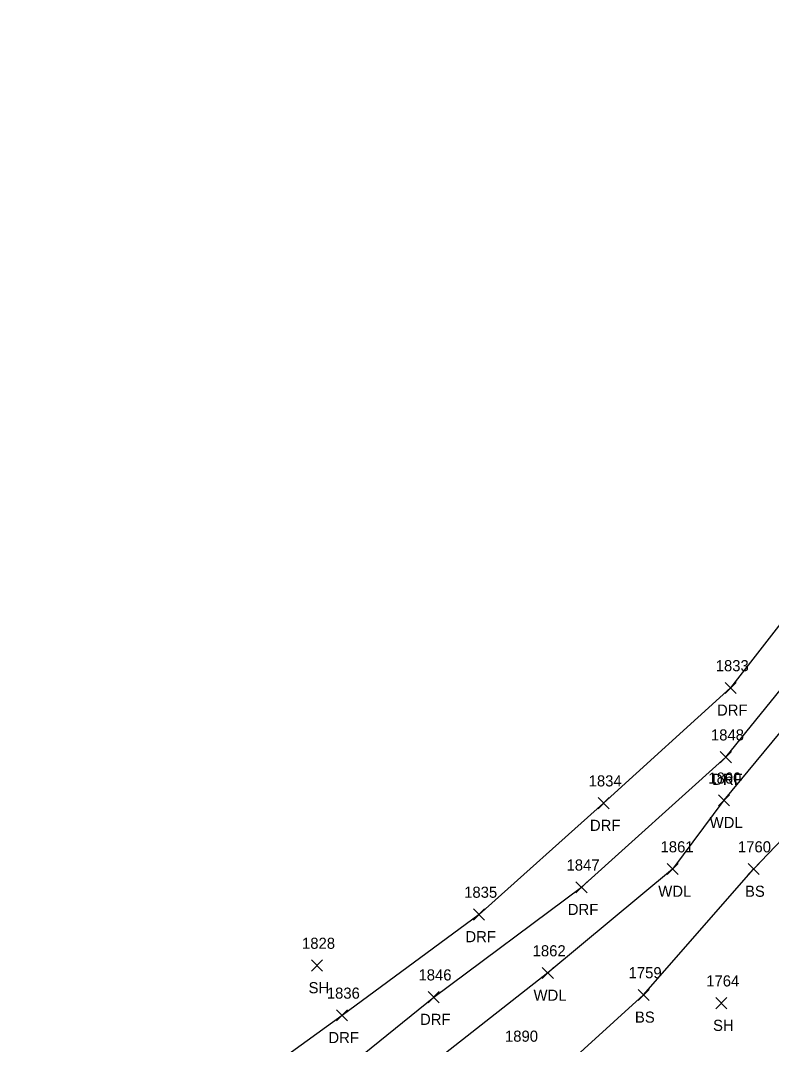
# Model space of a CAD drawing. Extents: x 1621633 to 1624015, y 417863 to 420979.
# Drawn here: x 1621756.1 to 1621891.2, y 418122.7 to 418307.1 of the extents above; entities that cross this region are included whole.
import ezdxf

# ---------------------------------------------------------------- set-up
doc = ezdxf.new("R2010")
doc.units = 0
for name, color, linetype in [('L_A', 7, 'Continuous'), ('L_I', 7, 'Continuous'), ('L_TIC', 7, 'Continuous'), ('LAWA', 7, 'Continuous'), ('LELB', 7, 'Continuous'), ('R_A', 7, 'Continuous'), ('R_I', 7, 'Continuous'), ('R_TIC', 7, 'Continuous'), ('RDF', 7, 'Continuous')]:
    doc.layers.add(name, color=color, linetype=linetype)

msp = doc.modelspace()

# ---------------------------------------------------------------- linework, layer by layer
at = {"layer": 'L_TIC'}
for points in [[(1621881.69, 418165.67), (1621883.69, 418167.67)], [(1621883.69, 418165.67), (1621881.69, 418167.67)], [(1621872.44, 418153.29), (1621874.44, 418155.29)], [(1621874.44, 418153.29), (1621872.44, 418155.29)], [(1621887.03, 418153.29), (1621889.03, 418155.29)], [(1621889.03, 418153.29), (1621887.03, 418155.29)], [(1621808.43, 418135.92), (1621810.43, 418137.92)], [(1621810.43, 418135.92), (1621808.43, 418137.92)], [(1621849.99, 418134.57), (1621851.99, 418136.57)], [(1621851.99, 418134.57), (1621849.99, 418136.57)], [(1621867.22, 418130.62), (1621869.22, 418132.62)], [(1621869.22, 418130.62), (1621867.22, 418132.62)], [(1621881.23, 418129.14), (1621883.23, 418131.14)], [(1621883.23, 418129.14), (1621881.23, 418131.14)]]:
    msp.add_lwpolyline(points, dxfattribs=at)
at = {"layer": 'LAWA'}
msp.add_lwpolyline([(1621956.58, 418284.61), (1621944.79, 418263.74), (1621937.99, 418240.81), (1621923.64, 418212.08), (1621903.11, 418191.44), (1621882.69, 418166.67), (1621873.44, 418154.29), (1621850.99, 418135.57), (1621826.17, 418116.06), (1621804.72, 418096.14), (1621776.82, 418074.39), (1621781.78, 418070.72), (1621808.71, 418078.7), (1621829.62, 418083.56), (1621862.33, 418091.33), (1621892.29, 418098.27), (1621914.93, 418102.81), (1621920.3, 418103.1), (1621927.79, 418103.9), (1621958.83, 418106.15)], dxfattribs=at)
at = {"layer": 'LELB'}
msp.add_lwpolyline([(1621837.73, 418093.38), (1621852.21, 418117.02), (1621868.22, 418131.62), (1621888.03, 418154.29), (1621907.66, 418174.83)], dxfattribs=at)
at = {"layer": 'R_TIC'}
for points in [[(1621882.89, 418185.91), (1621884.89, 418187.91)], [(1621884.89, 418185.91), (1621882.89, 418187.91)], [(1621882.03, 418173.44), (1621884.03, 418175.44)], [(1621884.03, 418173.44), (1621882.03, 418175.44)], [(1621860.02, 418165.16), (1621862.02, 418167.16)], [(1621862.02, 418165.16), (1621860.02, 418167.16)], [(1621856.04, 418150.01), (1621858.04, 418152.01)], [(1621858.04, 418150.01), (1621856.04, 418152.01)], [(1621837.61, 418145.11), (1621839.61, 418147.11)], [(1621839.61, 418145.11), (1621837.61, 418147.11)], [(1621829.45, 418130.22), (1621831.45, 418132.22)], [(1621831.45, 418130.22), (1621829.45, 418132.22)], [(1621812.95, 418126.94), (1621814.95, 418128.94)], [(1621814.95, 418126.94), (1621812.95, 418128.94)]]:
    msp.add_lwpolyline(points, dxfattribs=at)
at = {"layer": 'RDF'}
for points in [[(1621776.02, 418061.68), (1621769.52, 418069.9), (1621769.16, 418078.76), (1621780.25, 418093.21), (1621805.38, 418110.92), (1621830.45, 418131.22), (1621857.04, 418151.01), (1621883.03, 418174.44), (1621903.81, 418200.1), (1621921.4, 418229.54), (1621932.52, 418258.85), (1621944.51, 418286.74), (1621960.39, 418307.1)], [(1621940.59, 418295.72), (1621925.73, 418267.99), (1621914.41, 418239.65), (1621902.22, 418210.53), (1621883.89, 418186.91), (1621861.02, 418166.16), (1621838.61, 418146.11), (1621813.95, 418127.94), (1621789.4, 418110.13), (1621762.83, 418096.6), (1621756.07, 418081.78), (1621758.54, 418055.77)]]:
    msp.add_lwpolyline(points, dxfattribs=at)

# ---------------------------------------------------------------- texts
at = {"layer": 'L_A'}
for s, p in [('WDL', (1621880.11, 418161.67)), ('WDL', (1621870.86, 418149.29)), ('BS', (1621886.47, 418149.29)), ('SH', (1621807.92, 418131.92)), ('WDL', (1621848.41, 418130.57)), ('BS', (1621866.66, 418126.62)), ('SH', (1621880.72, 418125.14))]:
    msp.add_text(s, height=2, dxfattribs=at).set_placement(p)
at = {"layer": 'L_I'}
for s, p in [('1860', (1621879.87, 418169.67)), ('1861', (1621871.27, 418157.29)), ('1760', (1621885.2, 418157.29)), ('1828', (1621806.74, 418139.92)), ('1862', (1621848.25, 418138.57)), ('1759', (1621865.52, 418134.62)), ('1764', (1621879.49, 418133.14)), ('1890', (1621843.27, 418123.19))]:
    msp.add_text(s, height=2, dxfattribs=at).set_placement(p)
at = {"layer": 'R_A'}
for p in [(1621881.43, 418181.91), (1621880.57, 418169.44), (1621858.56, 418161.16), (1621854.58, 418146.01), (1621836.15, 418141.11), (1621827.98, 418126.22), (1621811.49, 418122.94)]:
    msp.add_text('DRF', height=2, dxfattribs=at).set_placement(p)
at = {"layer": 'R_I'}
for s, p in [('1833', (1621881.2, 418189.91)), ('1848', (1621880.34, 418177.44)), ('1834', (1621858.33, 418169.16)), ('1847', (1621854.35, 418154.01)), ('1835', (1621835.92, 418149.11)), ('1846', (1621827.7, 418134.22)), ('1836', (1621811.2, 418130.94))]:
    msp.add_text(s, height=2, dxfattribs=at).set_placement(p)

doc.saveas('drawing.dxf')
